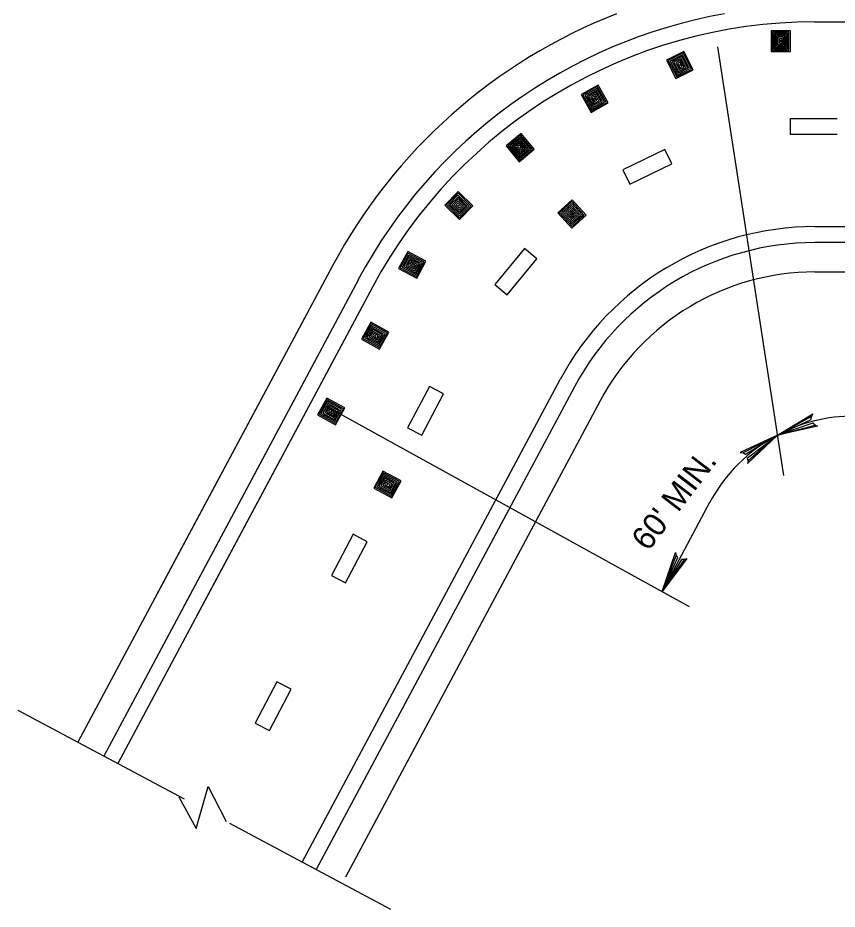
# Model space of a CAD drawing. Extents: x 639362 to 641108, y 298458 to 299646.
# Drawn here: x 639480.2 to 639586, y 299112.6 to 299227.7 of the extents above; entities that cross this region are included whole.
import ezdxf

# ---------------------------------------------------------------- set-up
doc = ezdxf.new("R2010")
doc.units = 0
doc.layers.add('2', color=7, linetype='Continuous')

msp = doc.modelspace()

# ---------------------------------------------------------------- linework, layer by layer
at = {"layer": '2'}
for p, q in [((639583.05, 299227.21), (639672.74, 299227.21)), ((639579.94, 299226.05), (639577.44, 299226.05)), ((639577.44, 299226.05), (639577.44, 299223.4)), ((639579.75, 299225.92), (639577.62, 299225.92)), ((639577.62, 299225.92), (639577.62, 299223.53)), ((639579.57, 299225.75), (639577.8, 299225.75)), ((639577.8, 299225.75), (639577.8, 299223.71)), ((639579.57, 299223.71), (639579.57, 299225.75)), ((639579.75, 299223.53), (639579.75, 299225.92)), ((639579.94, 299223.4), (639579.94, 299226.05)), ((639579.4, 299225.57), (639577.98, 299225.57)), ((639577.98, 299225.57), (639577.98, 299223.88)), ((639579.22, 299225.39), (639578.16, 299225.39)), ((639578.16, 299225.39), (639578.16, 299224.06)), ((639578.33, 299225.21), (639578.33, 299224.24)), ((639579.04, 299225.21), (639578.33, 299225.21)), ((639578.86, 299225.03), (639578.51, 299225.03)), ((639578.51, 299225.03), (639578.51, 299224.41)), ((639578.69, 299224.86), (639578.69, 299224.59)), ((639578.86, 299224.41), (639578.86, 299225.03)), ((639579.04, 299224.24), (639579.04, 299225.21)), ((639579.22, 299224.06), (639579.22, 299225.39)), ((639579.4, 299223.88), (639579.4, 299225.57)), ((639566.18, 299223.4), (639563.96, 299222.26)), ((639567.39, 299221.03), (639566.18, 299223.4)), ((639570.51, 299224), (639579.06, 299168.65)), ((639577.44, 299223.4), (639579.94, 299223.4)), ((639577.62, 299223.53), (639579.75, 299223.53)), ((639577.8, 299223.71), (639579.57, 299223.71)), ((639577.98, 299223.88), (639579.4, 299223.88)), ((639578.16, 299224.06), (639579.22, 299224.06)), ((639578.33, 299224.24), (639579.04, 299224.24)), ((639578.51, 299224.41), (639578.86, 299224.41)), ((639563.96, 299222.26), (639565.17, 299219.9)), ((639566.08, 299223.19), (639564.18, 299222.22)), ((639566, 299222.96), (639564.42, 299222.15)), ((639565.92, 299222.72), (639564.66, 299222.07)), ((639565.85, 299222.48), (639564.9, 299221.99)), ((639566.45, 299221.29), (639565.85, 299222.48)), ((639566.69, 299221.21), (639565.92, 299222.72)), ((639566.93, 299221.14), (639566, 299222.96)), ((639567.17, 299221.06), (639566.08, 299223.19)), ((639564.18, 299222.22), (639565.28, 299220.09)), ((639564.42, 299222.15), (639565.35, 299220.33)), ((639564.66, 299222.07), (639565.43, 299220.57)), ((639564.9, 299221.99), (639565.51, 299220.81)), ((639565.77, 299222.24), (639565.14, 299221.92)), ((639565.14, 299221.92), (639565.58, 299221.05)), ((639565.35, 299220.33), (639566.93, 299221.14)), ((639565.69, 299222), (639565.38, 299221.84)), ((639565.38, 299221.84), (639565.66, 299221.29)), ((639565.43, 299220.57), (639566.69, 299221.21)), ((639565.51, 299220.81), (639566.45, 299221.29)), ((639565.58, 299221.05), (639566.22, 299221.37)), ((639565.62, 299221.76), (639565.74, 299221.52)), ((639565.66, 299221.29), (639565.98, 299221.45)), ((639565.98, 299221.45), (639565.69, 299222)), ((639566.22, 299221.37), (639565.77, 299222.24)), ((639565.17, 299219.9), (639567.39, 299221.03)), ((639565.28, 299220.09), (639567.17, 299221.06)), ((639555.11, 299219.04), (639552.93, 299217.82)), ((639555.01, 299218.84), (639553.15, 299217.8)), ((639556.18, 299216.75), (639555.01, 299218.84)), ((639556.4, 299216.73), (639555.11, 299219.04)), ((639552.93, 299217.82), (639554.23, 299215.51)), ((639553.15, 299217.8), (639554.32, 299215.71)), ((639554.94, 299218.6), (639553.39, 299217.73)), ((639553.39, 299217.73), (639554.39, 299215.95)), ((639554.87, 299218.35), (639553.64, 299217.66)), ((639553.64, 299217.66), (639554.46, 299216.19)), ((639554.81, 299218.11), (639553.88, 299217.59)), ((639554.74, 299217.87), (639554.12, 299217.52)), ((639555.21, 299217.02), (639554.74, 299217.87)), ((639555.46, 299216.95), (639554.81, 299218.11)), ((639555.7, 299216.88), (639554.87, 299218.35)), ((639555.94, 299216.82), (639554.94, 299218.6)), ((639553.88, 299217.59), (639554.53, 299216.43)), ((639554.12, 299217.52), (639554.59, 299216.67)), ((639554.23, 299215.51), (639556.4, 299216.73)), ((639554.32, 299215.71), (639556.18, 299216.75)), ((639554.67, 299217.63), (639554.36, 299217.46)), ((639554.36, 299217.46), (639554.66, 299216.91)), ((639554.39, 299215.95), (639555.94, 299216.82)), ((639554.46, 299216.19), (639555.7, 299216.88)), ((639554.53, 299216.43), (639555.46, 299216.95)), ((639554.59, 299216.67), (639555.21, 299217.02)), ((639554.6, 299217.39), (639554.73, 299217.16)), ((639554.66, 299216.91), (639554.97, 299217.09)), ((639554.97, 299217.09), (639554.67, 299217.63)), ((639579.96, 299212.66), (639579.96, 299214.72)), ((639579.96, 299214.72), (639585.97, 299214.72)), ((639545.17, 299212.79), (639543.25, 299211.2)), ((639545.11, 299212.57), (639543.47, 299211.21)), ((639545.09, 299212.32), (639543.72, 299211.19)), ((639545.07, 299212.07), (639543.97, 299211.17)), ((639546.14, 299210.77), (639545.07, 299212.07)), ((639546.39, 299210.75), (639545.09, 299212.32)), ((639546.64, 299210.73), (639545.11, 299212.57)), ((639546.87, 299210.75), (639545.17, 299212.79)), ((639585.97, 299212.66), (639579.96, 299212.66)), ((639543.25, 299211.2), (639544.94, 299209.15)), ((639543.47, 299211.21), (639545, 299209.37)), ((639543.72, 299211.19), (639545.02, 299209.62)), ((639543.97, 299211.17), (639545.05, 299209.87)), ((639545.04, 299211.82), (639544.22, 299211.14)), ((639544.22, 299211.14), (639545.07, 299210.12)), ((639545.02, 299211.57), (639544.47, 299211.12)), ((639544.47, 299211.12), (639545.09, 299210.37)), ((639545, 299211.32), (639544.72, 299211.09)), ((639544.72, 299211.09), (639545.12, 299210.62)), ((639544.94, 299209.15), (639546.87, 299210.75)), ((639544.97, 299211.07), (639545.14, 299210.87)), ((639545.39, 299210.84), (639545, 299211.32)), ((639545.64, 299210.82), (639545.02, 299211.57)), ((639545.02, 299209.62), (639546.39, 299210.75)), ((639545.89, 299210.8), (639545.04, 299211.82)), ((639545.05, 299209.87), (639546.14, 299210.77)), ((639545.07, 299210.12), (639545.89, 299210.8)), ((639545.09, 299210.37), (639545.64, 299210.82)), ((639545.12, 299210.62), (639545.39, 299210.84)), ((639545, 299209.37), (639546.64, 299210.73)), ((639563.72, 299210.73), (639558.31, 299208.12)), ((639564.62, 299208.87), (639563.72, 299210.73)), ((639559.21, 299206.26), (639564.62, 299208.87)), ((639558.31, 299208.12), (639559.21, 299206.26)), ((639537.07, 299205.32), (639535.32, 299203.54)), ((639537.04, 299205.09), (639535.54, 299203.57)), ((639538.74, 299203.41), (639537.04, 299205.09)), ((639538.96, 299203.46), (639537.07, 299205.32)), ((639537.03, 299204.84), (639535.79, 299203.57)), ((639537.04, 299204.59), (639536.04, 299203.58)), ((639537.04, 299204.34), (639536.3, 299203.58)), ((639537.04, 299204.09), (639536.55, 299203.58)), ((639537.04, 299203.84), (639536.8, 299203.58)), ((639538.49, 299203.41), (639537.03, 299204.84)), ((639538.24, 299203.41), (639537.04, 299204.59)), ((639537.99, 299203.41), (639537.04, 299204.34)), ((639537.74, 299203.4), (639537.04, 299204.09)), ((639537.49, 299203.4), (639537.04, 299203.84)), ((639551.77, 299204.22), (639549.93, 299202.53)), ((639551.72, 299204), (639550.15, 299202.56)), ((639553.34, 299202.24), (639551.72, 299204)), ((639553.56, 299202.26), (639551.77, 299204.22)), ((639535.32, 299203.54), (639537.21, 299201.68)), ((639535.54, 299203.57), (639537.25, 299201.89)), ((639535.79, 299203.57), (639537.25, 299202.15)), ((639536.04, 299203.58), (639537.25, 299202.4)), ((639536.3, 299203.58), (639537.25, 299202.65)), ((639536.55, 299203.58), (639537.24, 299202.9)), ((639536.8, 299203.58), (639537.24, 299203.15)), ((639537.05, 299203.59), (639537.24, 299203.4)), ((639537.21, 299201.68), (639538.96, 299203.46)), ((639537.24, 299202.9), (639537.74, 299203.4)), ((639537.24, 299203.15), (639537.49, 299203.4)), ((639537.25, 299201.89), (639538.74, 299203.41)), ((639537.25, 299202.15), (639538.49, 299203.41)), ((639537.25, 299202.4), (639538.24, 299203.41)), ((639537.25, 299202.65), (639537.99, 299203.41)), ((639551.71, 299203.75), (639550.41, 299202.55)), ((639551.7, 299203.5), (639550.65, 299202.54)), ((639551.69, 299203.25), (639550.9, 299202.53)), ((639551.68, 299203), (639551.15, 299202.52)), ((639551.67, 299202.75), (639551.41, 299202.51)), ((639552.09, 299202.29), (639551.67, 299202.75)), ((639552.34, 299202.28), (639551.68, 299203)), ((639552.59, 299202.27), (639551.69, 299203.25)), ((639552.84, 299202.26), (639551.7, 299203.5)), ((639553.09, 299202.25), (639551.71, 299203.75)), ((639549.93, 299202.53), (639551.72, 299200.58)), ((639550.15, 299202.56), (639551.77, 299200.8)), ((639550.41, 299202.55), (639551.78, 299201.05)), ((639550.65, 299202.54), (639551.79, 299201.3)), ((639550.9, 299202.53), (639551.8, 299201.55)), ((639551.15, 299202.52), (639551.81, 299201.8)), ((639551.41, 299202.51), (639551.83, 299202.05)), ((639551.84, 299202.3), (639551.66, 299202.5)), ((639551.72, 299200.58), (639553.56, 299202.26)), ((639551.77, 299200.8), (639553.34, 299202.24)), ((639551.78, 299201.05), (639553.09, 299202.25)), ((639551.79, 299201.3), (639552.84, 299202.26)), ((639551.8, 299201.55), (639552.59, 299202.27)), ((639551.81, 299201.8), (639552.34, 299202.28)), ((639551.83, 299202.05), (639552.09, 299202.29)), ((639583.1, 299200.77), (639789.68, 299200.77)), ((639789.68, 299198.71), (639583.1, 299198.71)), ((639530.54, 299197.57), (639529.37, 299195.36)), ((639530.57, 299197.34), (639529.57, 299195.46)), ((639530.64, 299197.1), (639529.81, 299195.54)), ((639532.88, 299196.32), (639530.54, 299197.57)), ((639532.68, 299196.22), (639530.57, 299197.34)), ((639532.44, 299196.15), (639530.64, 299197.1)), ((639530.71, 299196.86), (639530.05, 299195.61)), ((639530.79, 299196.62), (639530.29, 299195.68)), ((639530.86, 299196.38), (639530.53, 299195.76)), ((639532.2, 299196.07), (639530.71, 299196.86)), ((639530.93, 299196.14), (639530.77, 299195.83)), ((639530.77, 299195.83), (639531.32, 299195.54)), ((639531.96, 299196), (639530.79, 299196.62)), ((639531.72, 299195.93), (639530.86, 299196.38)), ((639531.48, 299195.85), (639530.93, 299196.14)), ((639531.01, 299195.9), (639531.24, 299195.78)), ((639531.32, 299195.54), (639531.48, 299195.85)), ((639531.39, 299195.3), (639531.72, 299195.93)), ((639531.46, 299195.06), (639531.96, 299196)), ((639531.54, 299194.82), (639532.2, 299196.07)), ((639531.61, 299194.58), (639532.44, 299196.15)), ((639531.68, 299194.34), (639532.68, 299196.22)), ((639531.71, 299194.12), (639532.88, 299196.32)), ((639520.84, 299195.72), (639487.97, 299134.21)), ((639520.84, 299195.72), (639498.08, 299153.13)), ((639529.37, 299195.36), (639531.71, 299194.12)), ((639529.57, 299195.46), (639531.68, 299194.34)), ((639529.81, 299195.54), (639531.61, 299194.58)), ((639530.05, 299195.61), (639531.54, 299194.82)), ((639530.29, 299195.68), (639531.46, 299195.06)), ((639530.53, 299195.76), (639531.39, 299195.3)), ((639583.1, 299194.92), (639789.68, 299194.92)), ((639524.18, 299193.93), (639491.31, 299132.42)), ((639524.18, 299193.93), (639501.42, 299151.35)), ((639526, 299192.96), (639493.13, 299131.45)), ((639526, 299192.96), (639503.24, 299150.37)), ((639525.8, 299188.42), (639524.59, 299186.24)), ((639525.83, 299188.2), (639524.8, 299186.33)), ((639525.89, 299187.95), (639525.04, 299186.4)), ((639528.12, 299187.14), (639525.8, 299188.42)), ((639527.92, 299187.04), (639525.83, 299188.2)), ((639527.68, 299186.97), (639525.89, 299187.95)), ((639525.96, 299187.71), (639525.28, 299186.47)), ((639526.03, 299187.47), (639525.52, 299186.54)), ((639526.1, 299187.23), (639525.76, 299186.61)), ((639525.76, 299186.61), (639526.62, 299186.14)), ((639527.44, 299186.9), (639525.96, 299187.71)), ((639526.17, 299186.99), (639526, 299186.68)), ((639526, 299186.68), (639526.54, 299186.38)), ((639527.2, 299186.83), (639526.03, 299187.47)), ((639526.96, 299186.76), (639526.1, 299187.23)), ((639526.72, 299186.69), (639526.17, 299186.99)), ((639526.24, 299186.75), (639526.48, 299186.62)), ((639526.54, 299186.38), (639526.72, 299186.69)), ((639526.62, 299186.14), (639526.96, 299186.76)), ((639526.69, 299185.9), (639527.2, 299186.83)), ((639526.76, 299185.66), (639527.44, 299186.9)), ((639526.82, 299185.42), (639527.68, 299186.97)), ((639526.89, 299185.18), (639527.92, 299187.04)), ((639526.92, 299184.96), (639528.12, 299187.14)), ((639524.59, 299186.24), (639526.92, 299184.96)), ((639524.8, 299186.33), (639526.89, 299185.18)), ((639525.04, 299186.4), (639526.82, 299185.42)), ((639525.28, 299186.47), (639526.76, 299185.66)), ((639525.52, 299186.54), (639526.69, 299185.9)), ((639516.93, 299118.73), (639550.23, 299181.04)), ((639552.05, 299180.07), (639518.75, 299117.76)), ((639533.34, 299180.12), (639530.53, 299174.8)), ((639535.16, 299179.16), (639533.34, 299180.12)), ((639520.11, 299178.64), (639518.91, 299176.45)), ((639522.44, 299177.36), (639520.11, 299178.64)), ((639532.36, 299173.84), (639535.16, 299179.16)), ((639520.14, 299178.41), (639519.11, 299176.55)), ((639520.21, 299178.17), (639519.35, 299176.62)), ((639520.28, 299177.93), (639519.59, 299176.69)), ((639519.65, 299177.8), (639566.88, 299151.74)), ((639520.35, 299177.69), (639519.83, 299176.76)), ((639520.42, 299177.45), (639520.08, 299176.83)), ((639522.24, 299177.26), (639520.14, 299178.41)), ((639521.99, 299177.19), (639520.21, 299178.17)), ((639521.76, 299177.11), (639520.28, 299177.93)), ((639521.51, 299177.05), (639520.35, 299177.69)), ((639521.27, 299176.98), (639520.42, 299177.45)), ((639555.39, 299178.29), (639522.52, 299116.78)), ((639518.91, 299176.45), (639521.23, 299175.17)), ((639519.11, 299176.55), (639521.21, 299175.39)), ((639519.35, 299176.62), (639521.14, 299175.63)), ((639519.59, 299176.69), (639521.07, 299175.87)), ((639519.83, 299176.76), (639521, 299176.11)), ((639520.08, 299176.83), (639520.93, 299176.35)), ((639520.49, 299177.21), (639520.32, 299176.89)), ((639520.32, 299176.89), (639520.86, 299176.59)), ((639521.03, 299176.91), (639520.49, 299177.21)), ((639520.56, 299176.97), (639520.79, 299176.84)), ((639520.86, 299176.59), (639521.03, 299176.91)), ((639520.93, 299176.35), (639521.27, 299176.98)), ((639521, 299176.11), (639521.51, 299177.05)), ((639521.07, 299175.87), (639521.76, 299177.11)), ((639521.14, 299175.63), (639521.99, 299177.19)), ((639521.21, 299175.39), (639522.24, 299177.26)), ((639521.23, 299175.17), (639522.44, 299177.36)), ((639530.53, 299174.8), (639532.36, 299173.84)), ((639527.34, 299169.21), (639526.16, 299167.01)), ((639527.37, 299168.99), (639526.36, 299167.11)), ((639527.44, 299168.75), (639526.6, 299167.18)), ((639527.51, 299168.51), (639526.84, 299167.26)), ((639527.58, 299168.27), (639527.08, 299167.33)), ((639529.68, 299167.95), (639527.34, 299169.21)), ((639529.48, 299167.86), (639527.37, 299168.99)), ((639529.24, 299167.78), (639527.44, 299168.75)), ((639529, 299167.71), (639527.51, 299168.51)), ((639528.76, 299167.64), (639527.58, 299168.27)), ((639526.16, 299167.01), (639528.5, 299165.75)), ((639526.36, 299167.11), (639528.47, 299165.98)), ((639526.6, 299167.18), (639528.4, 299166.22)), ((639526.84, 299167.26), (639528.33, 299166.46)), ((639527.08, 299167.33), (639528.25, 299166.7)), ((639527.66, 299168.03), (639527.32, 299167.4)), ((639527.32, 299167.4), (639528.18, 299166.94)), ((639527.73, 299167.79), (639527.56, 299167.48)), ((639527.56, 299167.48), (639528.11, 299167.18)), ((639528.52, 299167.57), (639527.66, 299168.03)), ((639528.28, 299167.49), (639527.73, 299167.79)), ((639528.04, 299167.42), (639527.8, 299167.55)), ((639528.11, 299167.18), (639528.28, 299167.49)), ((639528.18, 299166.94), (639528.52, 299167.57)), ((639528.25, 299166.7), (639528.76, 299167.64)), ((639528.33, 299166.46), (639529, 299167.71)), ((639528.4, 299166.22), (639529.24, 299167.78)), ((639528.47, 299165.98), (639529.48, 299167.86)), ((639528.5, 299165.75), (639529.68, 299167.95)), ((639569.49, 299165.13), (639563.37, 299153.68)), ((639523.5, 299161.06), (639520.7, 299155.74)), ((639525.33, 299160.09), (639523.5, 299161.06)), ((639522.53, 299154.77), (639525.33, 299160.09)), ((639520.7, 299155.74), (639522.53, 299154.77)), ((639513.67, 299141.99), (639510.86, 299136.67)), ((639515.49, 299141.03), (639513.67, 299141.99)), ((639512.69, 299135.71), (639515.49, 299141.03)), ((639480.23, 299138.35), (639501.69, 299126.88)), ((639510.86, 299136.67), (639512.69, 299135.71)), ((639507.56, 299123.74), (639528.33, 299112.64)), ((639518.75, 299117.76), (639516.93, 299118.73))]:
    msp.add_line(p, q, dxfattribs=at)
msp.add_lwpolyline([(639541.8, 299193.28), (639543.4, 299191.97), (639547.21, 299196.62), (639545.61, 299197.93)], close=True, dxfattribs=at)
for points in [[(639583.13, 299175.13), (639582.82, 299175.4), (639578.26, 299173.85), (639583.13, 299175.13), (639583.44, 299175.02), (639578.26, 299173.85), (639582.63, 299175.86), (639582.66, 299176.26), (639578.26, 299173.85), (639582.82, 299176.58), (639582.66, 299176.26)], [(639574.47, 299170.53), (639574.42, 299170.93), (639578.26, 299173.85), (639574.47, 299170.53), (639574.38, 299170.2), (639578.26, 299173.85), (639574.15, 299171.35), (639573.8, 299171.55), (639578.26, 299173.85), (639573.44, 299171.6), (639573.8, 299171.55)], [(639566.28, 299157.79), (639565.87, 299157.8), (639563.37, 299153.68), (639566.28, 299157.79), (639566.59, 299157.91), (639563.37, 299153.68), (639565.42, 299158.03), (639565.19, 299158.35), (639563.37, 299153.68), (639565.11, 299158.7), (639565.19, 299158.35)], [(639501.02, 299127.14), (639503.25, 299123.07), (639504.81, 299128.49), (639507.1, 299123.96)]]:
    msp.add_lwpolyline(points, dxfattribs=at)
for centre, radius, start, end in [((639583.13, 299162.43), 70.63, 111.2803, 151.8821), ((639583.13, 299162.43), 66.85, 100.0708, 151.8821), ((639583.13, 299162.43), 64.78, 90.0716, 151.8821), ((639583.14, 299163.46), 37.31, 90.0716, 151.8821), ((639583.14, 299163.46), 35.25, 90.0716, 151.8821), ((639583.14, 299163.46), 31.46, 90.0716, 151.8821), ((639588.17, 299155.14), 21.17, 90.0716, 117.9286), ((639588.17, 299155.14), 21.17, 117.9286, 151.8821)]:
    msp.add_arc(centre, radius, start, end, dxfattribs=at)

# ---------------------------------------------------------------- texts
msp.add_text("60' MIN.", height=3, rotation=52.4618, dxfattribs=at).set_placement((639561.57, 299158.74))

doc.saveas('drawing.dxf')
